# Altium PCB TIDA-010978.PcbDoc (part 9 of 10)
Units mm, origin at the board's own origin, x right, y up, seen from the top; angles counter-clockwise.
Board outline 243.95 x 94.85 mm, 4 copper layers (Top Layer, Mid Layer 1, Mid Layer 2, Bottom Layer), stack 1.623 mm thick; 865 components, 374 nets, 2308 pads, 2132 vias.
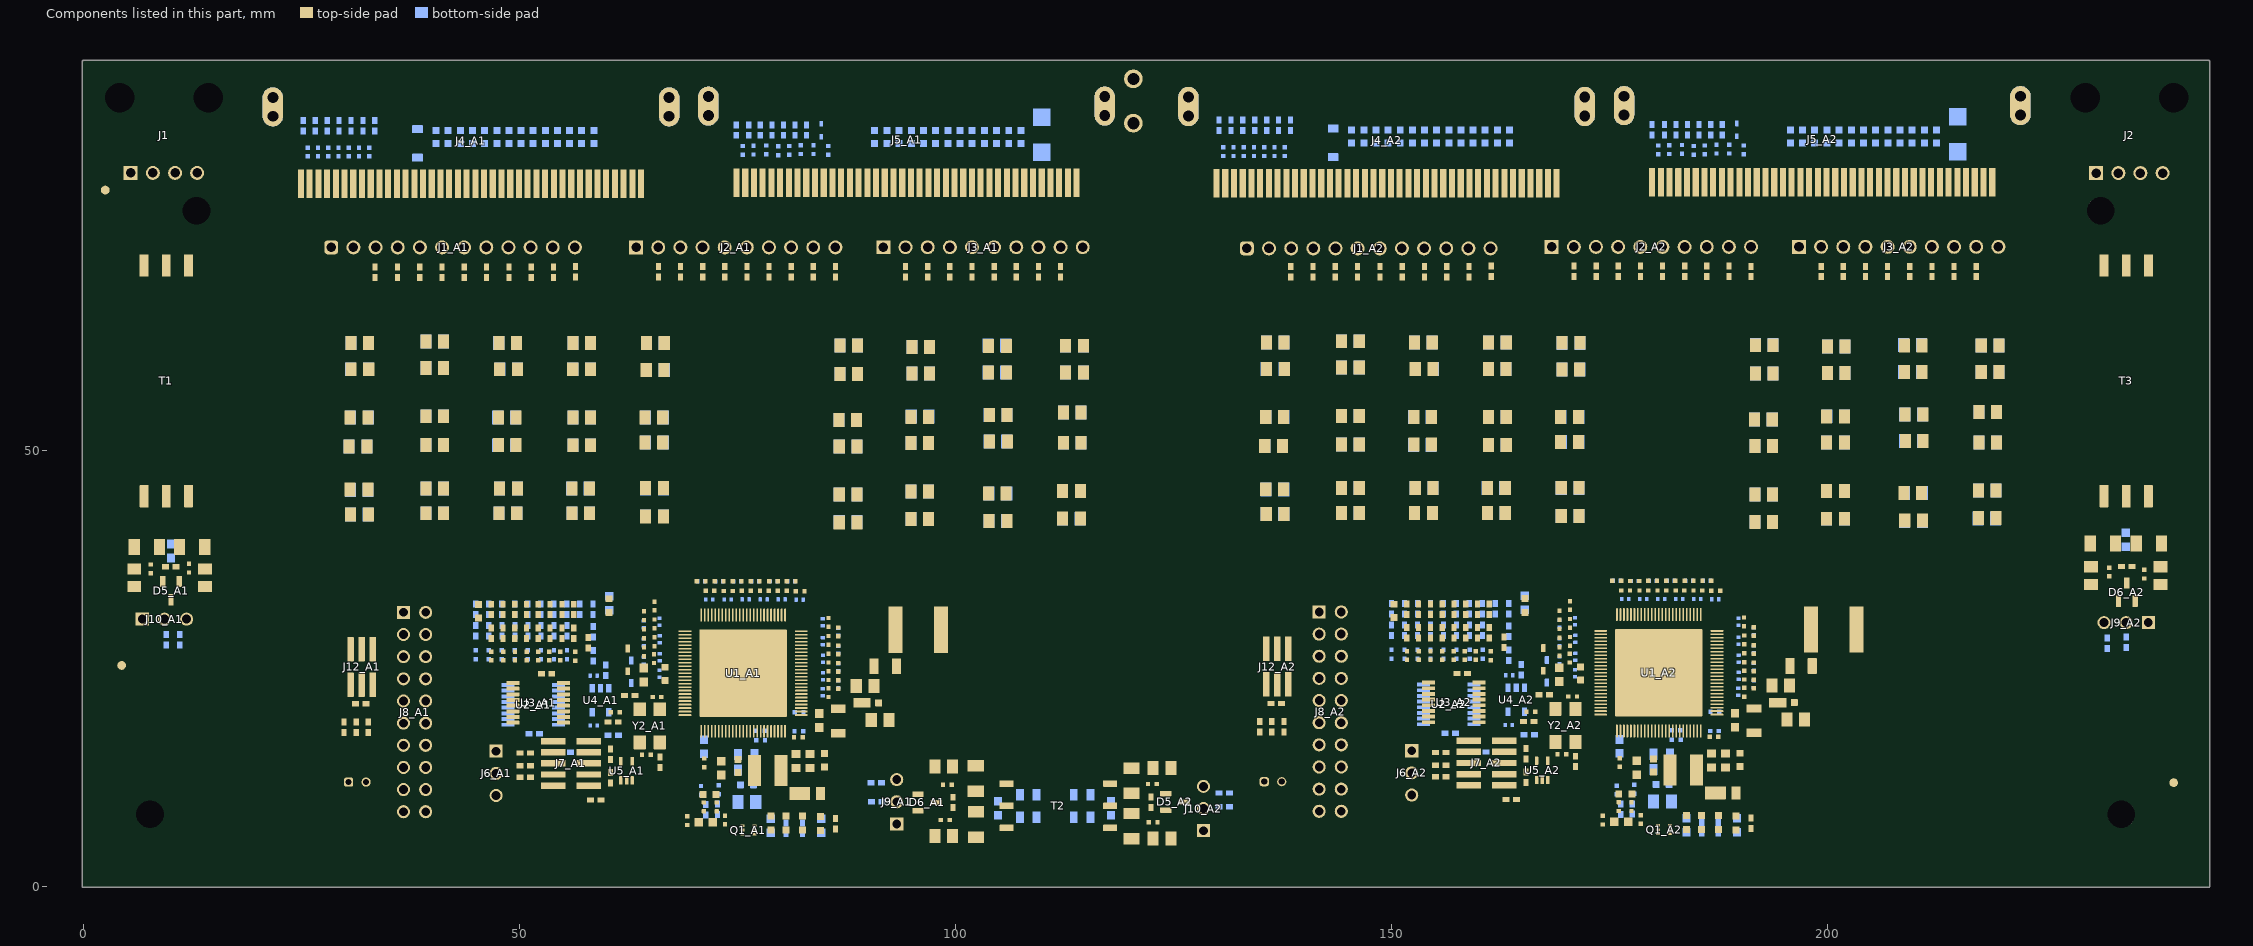
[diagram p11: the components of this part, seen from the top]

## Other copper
Top Layer:
  region net CB20_A2: 204.464,57.058 201.292,57.058 201.292,63.945 204.464,63.945
  region net CELL20_A2: 200.886,57.058 197.715,57.058 197.715,63.945 200.886,63.945
  region net CB17_A2: 196.058,56.967 192.886,56.967 192.886,63.854 196.058,63.854
  region net CELL17_A2: 192.48,56.967 189.308,56.967 189.308,63.854 192.48,63.854
  region net CB14_A2: 174.013,57.338 170.841,57.338 170.841,64.225 174.013,64.225
  region net CELL14_A2: 170.435,57.338 167.263,57.338 167.263,64.225 170.435,64.225
  pour cut-out: 198.148,82.352 198.148,83.282 198.953,84.087 212.953,84.087 213.996,83.044 213.996,82.198
  region net CB26_A2: 221.919,57.058 218.748,57.058 218.748,63.945 221.919,63.945
  region net CELL26_A2: 218.342,57.058 215.17,57.058 215.17,63.945 218.342,63.945
  region net CB23_A2: 213.251,57.058 210.08,57.058 210.08,63.945 213.251,63.945
  region net CELL23_A2: 209.674,57.058 206.502,57.058 206.502,63.945 209.674,63.945
  region net CELL25_A2: 218.273,49.233 215.101,49.233 215.101,56.12 218.273,56.12
  region net CB22_A2: 213.359,49.078 210.188,49.078 210.188,55.965 213.359,55.965
  region net CELL22_A2: 209.782,49.078 206.61,49.078 206.61,55.965 209.782,55.965
  region net CB24_A2: 221.72,40.608 218.548,40.608 218.548,47.495 221.72,47.495
  region net CELL24_A2: 218.143,40.608 214.971,40.608 214.971,47.495 218.143,47.495
  region net CB21_A2: 213.229,40.453 210.058,40.453 210.058,47.34 213.229,47.34
  region net CELL21_A2: 209.652,40.453 206.48,40.453 206.48,47.34 209.652,47.34
  region net CB19_A2: 204.518,49.062 201.347,49.062 201.347,55.949 204.518,55.949
  region net CELL19_A2: 200.941,49.062 197.769,49.062 197.769,55.949 200.941,55.949
  region net CB16_A2: 196.144,48.79 192.973,48.79 192.973,55.677 196.144,55.677
  region net CELL16_A2: 192.567,48.79 189.395,48.79 189.395,55.677 192.567,55.677
  region net CB18_A2: 204.388,40.437 201.217,40.437 201.217,47.324 204.388,47.324
  region net CELL18_A2: 200.811,40.437 197.639,40.437 197.639,47.324 200.811,47.324
  region net CB15_A2: 196.014,40.165 192.843,40.165 192.843,47.052 196.014,47.052
  region net CELL15_A2: 192.437,40.165 189.265,40.165 189.265,47.052 192.437,47.052
  pour cut-out: 148.223,82.339 148.223,78.896 143.417,78.896 139.729,75.209 137.264,75.209 134.449,72.394 134.449,67.325 140.505,67.325 142.586,65.245 167.392,65.245 167.392,65.024 168.207,64.209 175.49,64.209 175.49,39.879 174.974,39.363 168.198,39.363 168.198,39.361 166.645,37.591 166.645,27.723 168.492,25.876 171.69,25.876 173.327,24.238 173.327,24.099 174.373,24.099 174.747,24.473 174.607,24.614 174.607,30.549 185.568,30.549 186.466,29.651 186.707,29.651 186.707,22.852 186.03,22.175 185.858,22.175 185.858,19.366 186.73,18.495 192.295,18.474 192.865,17.841 200.704,17.841 200.704,25.885 202.072,25.885 202.072,32.583 202.091,32.603 201.407,33.286 196.716,33.286 196.716,35.241 197.412,35.937 225.967,35.937 225.967,67.262 222.842,70.387 222.842,75.612 219.112,75.612 215.892,78.832 215.892,82.033
  region net CB12_A2: 173.86,40.725 170.689,40.725 170.689,47.612 173.86,47.612
  region net CB13_A2: 173.764,49.038 170.592,49.038 170.592,55.925 173.764,55.925
  region net CELL12_A2: 170.283,40.725 167.111,40.725 167.111,47.612 170.283,47.612
  region net CELL13_A2: 170.187,49.038 167.015,49.038 167.015,55.925 170.187,55.925
  region net CB25_A2: 221.85,49.233 218.678,49.233 218.678,56.12 221.85,56.12
  pour cut-out: 148.223,82.552 148.223,83.482 149.028,84.287 163.028,84.287 164.071,83.244 164.071,82.398
  region net CB11_A2: 165.607,57.507 162.435,57.507 162.435,64.393 165.607,64.393
  region net CELL11_A2: 162.03,57.507 158.858,57.507 158.858,64.393 162.03,64.393
  region net CB8_A2: 157.082,57.507 153.91,57.507 153.91,64.393 157.082,64.393
  region net CELL8_A2: 153.505,57.507 150.333,57.507 150.333,64.393 153.505,64.393
  region net CB5_A2: 148.582,57.507 145.41,57.507 145.41,64.393 148.582,64.393
  region net CELL5_A2: 145.005,57.507 141.833,57.507 141.833,64.393 145.005,64.393
  region net CB2_A2: 140.072,57.566 136.9,57.566 136.9,64.453 140.072,64.453
  region net CELL2_A2: 136.494,57.566 133.323,57.566 133.323,64.453 136.494,64.453
  region net CB10_A2: 165.477,49.007 162.305,49.007 162.305,55.893 165.477,55.893
  region net CELL10_A2: 161.9,49.007 158.728,49.007 158.728,55.893 161.9,55.893
  region net CB9_A2: 165.573,40.693 162.401,40.693 162.401,47.58 165.573,47.58
  region net CELL9_A2: 161.996,40.693 158.824,40.693 158.824,47.58 161.996,47.58
  region net CB7_A2: 156.952,49.007 153.78,49.007 153.78,55.893 156.952,55.893
  pour cut-out: 175.49,64.209 174.416,65.283 143.124,65.283 141.374,67.034 131.669,67.034 131.669,41.085 133.404,39.35 175.765,39.35 175.765,40.195 176.838,41.267 176.838,64.146
  region net CELL7_A2: 153.375,49.007 150.203,49.007 150.203,55.893 153.375,55.893
  region net CB6_A2: 157.048,40.693 153.876,40.693 153.876,47.58 157.048,47.58
  region net CELL6_A2: 153.471,40.693 150.299,40.693 150.299,47.58 153.471,47.58
  region net CELL0_A2: 136.446,40.693 133.274,40.693 133.274,47.58 136.446,47.58
  region net CELL1_A2: 136.35,49.007 133.178,49.007 133.178,55.893 136.35,55.893
  region net CB0_A2: 139.856,40.693 136.685,40.693 136.685,47.58 139.856,47.58
  region net CB1_A2: 139.927,49.007 136.755,49.007 136.755,55.893 139.927,55.893
  region net CB4_A2: 148.452,49.007 145.28,49.007 145.28,55.893 148.452,55.893
  region net CELL4_A2: 144.875,49.007 141.703,49.007 141.703,55.893 144.875,55.893
  region net CB3_A2: 148.548,40.693 145.376,40.693 145.376,47.58 148.548,47.58
  region net CELL3_A2: 144.971,40.693 141.799,40.693 141.799,47.58 144.971,47.58
  pour cut-out: 183.606,16.121 183.472,15.987 183.472,10.912 185.33,10.912 185.371,10.871 185.371,9.318 188.529,9.318 188.908,9.698 188.908,12.108 189.507,12.135 189.495,16.157
  region net SW_A2: 184.189,11.77 184.189,15.51 184.394,15.715 187.232,15.715 187.232,12.794 187.232,12.673 188.325,11.58 188.315,11.58 188.325,10.289 188.226,10.19 185.915,10.19 185.915,11.24 185.385,11.77
  pour cut-out: 148.223,82.427 148.223,78.896 143.417,78.896 139.729,75.209 137.264,75.209 134.449,72.394 134.449,67.325 140.505,67.325 142.586,65.245 167.392,65.245 167.392,65.024 168.207,64.209 175.49,64.209 175.49,39.879 174.974,39.363 168.198,39.363 168.198,39.361 166.645,37.591 166.645,27.723 168.492,25.876 171.69,25.876 173.327,24.238 173.327,24.099 174.373,24.099 174.747,24.473 174.607,24.614 174.607,30.549 185.568,30.549 186.466,29.651 186.707,29.651 186.707,22.852 186.03,22.175 185.858,22.175 185.858,19.366 186.538,18.686 192.284,18.686 194.548,17.536 200.704,17.545 200.704,25.885 202.072,25.885 202.072,32.583 202.091,32.603 201.407,33.286 196.716,33.286 196.716,35.241 197.412,35.937 225.967,35.937 225.967,67.262 222.842,70.387 222.842,75.612 219.112,75.612 215.892,78.832 215.892,82.122
  pour cut-out: 43.223,82.289 43.223,78.846 38.417,78.846 34.729,75.159 32.264,75.159 29.449,72.344 29.449,67.275 35.505,67.275 37.586,65.195 62.392,65.195 62.392,64.974 63.207,64.159 70.49,64.159 70.49,39.829 69.974,39.313 63.198,39.313 63.198,39.311 61.645,37.541 61.645,27.673 63.492,25.826 66.69,25.826 68.327,24.188 68.327,24.049 69.373,24.049 69.747,24.423 69.607,24.564 69.607,30.499 80.568,30.499 81.466,29.601 81.707,29.601 81.707,22.802 81.03,22.125 80.858,22.125 80.858,19.316 81.73,18.445 87.295,18.424 87.997,17.644 95.704,17.644 95.704,25.835 97.072,25.835 97.072,32.533 97.091,32.553 96.407,33.236 91.716,33.236 91.716,35.191 92.412,35.887 120.967,35.887 120.967,67.212 117.842,70.337 117.842,75.562 114.112,75.562 110.892,78.782 110.892,81.983
  pour cut-out: 183.606,16.121 183.472,15.987 183.472,10.912 185.33,10.912 185.371,10.871 185.371,9.318 188.529,9.318 188.908,9.698 188.908,12.108 189.507,12.135 189.495,16.157
  pour cut-out: 78.606,16.071 78.472,15.937 78.472,10.862 80.33,10.862 80.371,10.821 80.371,9.268 83.529,9.268 83.908,9.648 83.908,12.058 84.507,12.085 84.495,16.107
  region net SW_A1: 79.189,11.72 79.189,15.46 79.394,15.665 82.232,15.665 82.232,12.744 82.232,12.623 83.325,11.53 83.315,11.53 83.325,10.239 83.226,10.14 80.915,10.14 80.915,11.19 80.385,11.72
  pour cut-out: 106.393,15.358 106.393,3.936 117.032,3.936 117.032,15.358
  pour cut-out: 106.401,15.465 106.401,4.043 117.039,4.043 117.039,15.465
  pour cut-out: 198.148,82.352 198.148,84.087 213.996,84.087 213.996,82.198
  pour cut-out: 175.49,64.209 174.416,65.283 143.124,65.283 141.374,67.034 131.669,67.034 131.669,41.085 133.404,39.35 175.765,39.35 175.765,40.195 176.838,41.267 176.838,64.146
  pour cut-out: 148.223,82.552 148.223,83.482 149.028,84.287 163.028,84.287 164.071,83.244 164.071,82.398
  pour cut-out: 162.636,25.219 168.106,25.219 168.433,24.892 168.433,21.879 170.055,21.879 170.855,22.678 172.974,22.678 173.541,22.112 174.828,22.112 174.985,21.955 174.985,21.687 174.717,21.687 174.514,21.484 173.336,21.484 172.59,20.739 172.59,14.819 168.497,10.725 168.497,10.461 167.719,9.683 162.648,9.683
  region net CB10_A1: 60.477,48.957 57.305,48.957 57.305,55.843 60.477,55.843
  region net CB7_A1: 51.952,48.957 48.78,48.957 48.78,55.843 51.952,55.843
  region net CELL10_A1: 56.9,48.957 53.728,48.957 53.728,55.843 56.9,55.843
  region net CB8_A1: 52.082,57.457 48.91,57.457 48.91,64.343 52.082,64.343
  region net CELL11_A1: 57.03,57.457 53.858,57.457 53.858,64.343 57.03,64.343
  region net CB11_A1: 60.607,57.457 57.435,57.457 57.435,64.343 60.607,64.343
  region net CELL4_A1: 39.875,48.957 36.703,48.957 36.703,55.843 39.875,55.843
  region net CB4_A1: 43.452,48.957 40.28,48.957 40.28,55.843 43.452,55.843
  region net CELL5_A1: 40.005,57.457 36.833,57.457 36.833,64.343 40.005,64.343
  region net CB5_A1: 43.582,57.457 40.41,57.457 40.41,64.343 43.582,64.343
  region net CELL7_A1: 48.375,48.957 45.203,48.957 45.203,55.843 48.375,55.843
  region net CELL8_A1: 48.505,57.457 45.333,57.457 45.333,64.343 48.505,64.343
  region net CELL2_A1: 31.494,57.516 28.323,57.516 28.323,64.403 31.494,64.403
  region net CELL1_A1: 31.35,48.957 28.178,48.957 28.178,55.843 31.35,55.843
  region net CELL0_A1: 31.446,40.643 28.274,40.643 28.274,47.53 31.446,47.53
  region net CB22_A1: 108.359,49.028 105.188,49.028 105.188,55.915 108.359,55.915
  region net CB19_A1: 99.518,49.012 96.347,49.012 96.347,55.899 99.518,55.899
  region net CELL22_A1: 104.782,49.028 101.61,49.028 101.61,55.915 104.782,55.915
  region net CB24_A1: 116.72,40.558 113.548,40.558 113.548,47.445 116.72,47.445
  region net CELL24_A1: 113.143,40.558 109.971,40.558 109.971,47.445 113.143,47.445
  region net CELL25_A1: 113.273,49.183 110.101,49.183 110.101,56.07 113.273,56.07
  region net CB25_A1: 116.85,49.183 113.678,49.183 113.678,56.07 116.85,56.07
  region net CB12_A1: 68.86,40.675 65.689,40.675 65.689,47.562 68.86,47.562
  region net CELL21_A1: 104.652,40.403 101.48,40.403 101.48,47.29 104.652,47.29
  region net CELL15_A1: 87.437,40.115 84.265,40.115 84.265,47.002 87.437,47.002
  region net CB15_A1: 91.014,40.115 87.843,40.115 87.843,47.002 91.014,47.002
  region net CELL16_A1: 87.567,48.74 84.395,48.74 84.395,55.627 87.567,55.627
  region net CELL26_A1: 113.342,57.008 110.17,57.008 110.17,63.895 113.342,63.895
  region net CELL20_A1: 95.886,57.008 92.715,57.008 92.715,63.895 95.886,63.895
  region net CB20_A1: 99.464,57.008 96.292,57.008 96.292,63.895 99.464,63.895
  region net CELL23_A1: 104.674,57.008 101.502,57.008 101.502,63.895 104.674,63.895
  region net CB23_A1: 108.251,57.008 105.08,57.008 105.08,63.895 108.251,63.895
  region net CELL19_A1: 95.941,49.012 92.769,49.012 92.769,55.899 95.941,55.899
  region net CB16_A1: 91.144,48.74 87.973,48.74 87.973,55.627 91.144,55.627
  region net CB26_A1: 116.919,57.008 113.748,57.008 113.748,63.895 116.919,63.895
  region net CB21_A1: 108.229,40.403 105.058,40.403 105.058,47.29 108.229,47.29
  region net CELL17_A1: 87.48,56.917 84.308,56.917 84.308,63.804 87.48,63.804
  region net CB17_A1: 91.058,56.917 87.886,56.917 87.886,63.804 91.058,63.804
  region net CB1_A1: 34.927,48.957 31.755,48.957 31.755,55.843 34.927,55.843
  region net CB2_A1: 35.072,57.516 31.9,57.516 31.9,64.403 35.072,64.403
  region net CB18_A1: 99.388,40.387 96.217,40.387 96.217,47.274 99.388,47.274
  region net CELL18_A1: 95.811,40.387 92.639,40.387 92.639,47.274 95.811,47.274
  region net CB0_A1: 34.856,40.643 31.685,40.643 31.685,47.53 34.856,47.53
  region net CB13_A1: 68.764,48.988 65.592,48.988 65.592,55.875 68.764,55.875
  region net CELL13_A1: 65.187,48.988 62.015,48.988 62.015,55.875 65.187,55.875
  region net CELL14_A1: 65.435,57.288 62.263,57.288 62.263,64.175 65.435,64.175
  region net CB14_A1: 69.013,57.288 65.841,57.288 65.841,64.175 69.013,64.175
  region net CELL3_A1: 39.971,40.643 36.799,40.643 36.799,47.53 39.971,47.53
  region net CELL12_A1: 65.283,40.675 62.111,40.675 62.111,47.562 65.283,47.562
  region net CB9_A1: 60.573,40.643 57.401,40.643 57.401,47.53 60.573,47.53
  region net CB3_A1: 43.548,40.643 40.376,40.643 40.376,47.53 43.548,47.53
  region net CELL6_A1: 48.471,40.643 45.299,40.643 45.299,47.53 48.471,47.53
  region net CB6_A1: 52.048,40.643 48.876,40.643 48.876,47.53 52.048,47.53
  region net CELL9_A1: 56.996,40.643 53.824,40.643 53.824,47.53 56.996,47.53
  pour cut-out: 70.49,64.159 69.416,65.233 38.124,65.233 36.374,66.984 26.669,66.984 26.669,41.035 28.404,39.3 70.765,39.3 70.765,40.145 71.838,41.217 71.838,64.096
  pour cut-out: 93.148,82.302 93.148,84.037 108.996,84.037 108.996,82.148
  pour cut-out: 43.223,82.502 43.223,83.432 44.028,84.237 58.028,84.237 59.071,83.194 59.071,82.348
  text ".Layer_Name" at 14.656,-21.806 h1.52
Mid Layer 1:
  pour cut-out: 195.707,74.642 194.984,74.642 194.501,74.158 194.501,72.086 195.16,71.427 221.981,71.427 221.981,74.752 221.756,74.977 195.695,74.977
  pour cut-out: 167.345,74.629 166.623,74.629 166.139,74.145 166.139,72.072 166.798,71.414 193.62,71.414 193.62,74.738 193.395,74.964 167.334,74.964
  pour cut-out: 195.707,74.642 194.984,74.642 194.501,74.158 194.501,72.086 195.16,71.427 221.981,71.427 221.981,74.752 221.756,74.977 195.695,74.977
  pour cut-out: 197.565,83.567 198.042,84.045 214.579,84.045 214.579,82.106 197.565,82.106
  pour cut-out: 145.56,83.786 146.037,84.263 163.291,84.263 163.291,82.325 145.56,82.325
  pour cut-out: 137.471,74.629 136.748,74.629 136.265,74.145 136.265,72.072 136.924,71.414 163.746,71.414 163.746,74.738 163.52,74.964 137.459,74.964
  pour cut-out: 106.382,15.34 106.382,3.919 117.021,3.919 117.021,15.34
  pour cut-out: 167.345,74.629 166.623,74.629 166.139,74.145 166.139,72.072 166.798,71.414 193.62,71.414 193.62,74.738 193.395,74.964 167.334,74.964
  pour cut-out: 197.565,83.567 198.042,84.045 214.579,84.045 214.579,82.106 197.565,82.106
  pour cut-out: 137.471,74.629 136.748,74.629 136.265,74.145 136.265,72.072 136.924,71.414 163.746,71.414 163.746,74.738 163.52,74.964 137.459,74.964
  pour cut-out: 145.56,83.786 146.037,84.263 163.291,84.263 163.291,82.325 145.56,82.325
  pour cut-out: 32.471,74.579 31.748,74.579 31.265,74.095 31.265,72.023 31.924,71.364 58.746,71.364 58.746,74.688 58.52,74.914 32.459,74.914
  pour cut-out: 62.345,74.579 61.623,74.579 61.139,74.095 61.139,72.023 61.798,71.364 88.62,71.364 88.62,74.688 88.395,74.914 62.334,74.914
  pour cut-out: 90.707,74.592 89.984,74.592 89.501,74.108 89.501,72.036 90.16,71.377 116.981,71.377 116.981,74.702 116.756,74.927 90.695,74.927
  pour cut-out: 40.56,83.736 41.037,84.213 58.291,84.213 58.291,82.275 40.56,82.275
  pour cut-out: 92.565,83.517 93.042,83.995 109.579,83.995 109.579,82.056 92.565,82.056
Mid Layer 2:
  pour cut-out: 195.715,74.615 194.992,74.615 194.509,74.132 194.509,72.059 195.168,71.4 221.99,71.4 221.99,74.725 221.764,74.95 195.703,74.95
  pour cut-out: 197.573,83.541 198.051,84.018 214.587,84.018 214.587,82.079 197.573,82.079
  pour cut-out: 167.353,74.602 166.631,74.602 166.147,74.118 166.147,72.046 166.806,71.387 193.628,71.387 193.628,74.712 193.403,74.937 167.342,74.937
  pour cut-out: 145.568,83.76 146.045,84.237 163.299,84.237 163.299,82.298 145.568,82.298
  pour cut-out: 137.479,74.602 136.757,74.602 136.273,74.118 136.273,72.046 136.932,71.387 163.754,71.387 163.754,74.712 163.528,74.937 137.467,74.937
  pour cut-out: 106.382,15.34 106.382,3.919 117.021,3.919 117.021,15.34
  pour cut-out: 197.573,83.541 198.051,84.018 214.587,84.018 214.587,82.079 197.573,82.079
  pour cut-out: 145.568,83.76 146.045,84.237 163.299,84.237 163.299,82.298 145.568,82.298
  pour cut-out: 167.353,74.602 166.631,74.602 166.147,74.118 166.147,72.046 166.806,71.387 193.628,71.387 193.628,74.712 193.403,74.937 167.342,74.937
  pour cut-out: 137.479,74.602 136.757,74.602 136.273,74.118 136.273,72.046 136.932,71.387 163.754,71.387 163.754,74.712 163.528,74.937 137.467,74.937
  pour cut-out: 90.715,74.565 89.992,74.565 89.509,74.082 89.509,72.009 90.168,71.35 116.99,71.35 116.99,74.675 116.764,74.9 90.703,74.9
  pour cut-out: 62.353,74.552 61.631,74.552 61.147,74.068 61.147,71.996 61.806,71.337 88.628,71.337 88.628,74.662 88.403,74.887 62.342,74.887
  pour cut-out: 32.479,74.552 31.757,74.552 31.273,74.068 31.273,71.996 31.932,71.337 58.754,71.337 58.754,74.662 58.528,74.887 32.467,74.887
  pour cut-out: 40.568,83.71 41.045,84.187 58.299,84.187 58.299,82.248 40.568,82.248
  pour cut-out: 92.573,83.491 93.05,83.968 109.587,83.968 109.587,82.029 92.573,82.029
Bottom Layer:
  pour cut-out: 195.715,74.615 194.992,74.615 194.509,74.132 194.509,72.059 195.168,71.4 221.99,71.4 221.99,74.725 221.764,74.95 195.703,74.95
  pour cut-out: 90.715,74.565 89.992,74.565 89.509,74.082 89.509,72.009 90.168,71.35 116.99,71.35 116.99,74.675 116.764,74.9 90.703,74.9
  pour cut-out: 176.597,18.521 176.322,18.796 172.94,18.796 171.651,17.507 170.249,17.507 170.155,17.413 170.155,11.127 170.811,10.471 174.163,10.471 174.581,11.127 174.581,11.565 174.581,16.762 175.013,16.762 175.326,17.507 176.094,17.6 176.597,17.6
  region net CB10_A2: 165.477,49.007 162.305,49.007 162.305,55.893 165.477,55.893
  region net CB9_A2: 165.573,40.693 162.401,40.693 162.401,47.58 165.573,47.58
  region net CELL10_A2: 161.9,49.007 158.728,49.007 158.728,55.893 161.9,55.893
  region net CB7_A2: 156.952,49.007 153.78,49.007 153.78,55.893 156.952,55.893
  region net CELL7_A2: 153.375,49.007 150.203,49.007 150.203,55.893 153.375,55.893
  region net CELL9_A2: 161.996,40.693 158.824,40.693 158.824,47.58 161.996,47.58
  region net CB6_A2: 157.048,40.693 153.876,40.693 153.876,47.58 157.048,47.58
  region net CELL6_A2: 153.471,40.693 150.299,40.693 150.299,47.58 153.471,47.58
  region net CB4_A2: 148.452,49.007 145.28,49.007 145.28,55.893 148.452,55.893
  region net CELL4_A2: 144.875,49.007 141.703,49.007 141.703,55.893 144.875,55.893
  region net CB3_A2: 148.548,40.693 145.376,40.693 145.376,47.58 148.548,47.58
  region net CELL3_A2: 144.971,40.693 141.799,40.693 141.799,47.58 144.971,47.58
  region net CB2_A2: 140.057,57.632 136.885,57.632 136.885,64.518 140.057,64.518
  region net CELL2_A2: 136.48,57.632 133.308,57.632 133.308,64.518 136.48,64.518
  region net CB1_A2: 139.927,49.007 136.755,49.007 136.755,55.893 139.927,55.893
  region net CELL1_A2: 136.35,49.007 133.178,49.007 133.178,55.893 136.35,55.893
  region net CB0_A2: 139.856,40.693 136.685,40.693 136.685,47.58 139.856,47.58
  region net CELL0_A2: 136.446,40.693 133.274,40.693 133.274,47.58 136.446,47.58
  region net CELL23_A2: 209.674,57.058 206.502,57.058 206.502,63.945 209.674,63.945
  region net CB20_A2: 204.464,57.058 201.292,57.058 201.292,63.945 204.464,63.945
  region net CELL20_A2: 200.886,57.058 197.715,57.058 197.715,63.945 200.886,63.945
  region net CELL22_A2: 209.782,49.078 206.61,49.078 206.61,55.965 209.782,55.965
  region net CELL19_A2: 200.941,49.062 197.769,49.062 197.769,55.949 200.941,55.949
  region net CB19_A2: 204.518,49.062 201.347,49.062 201.347,55.949 204.518,55.949
  region net CB17_A2: 196.058,56.967 192.886,56.967 192.886,63.854 196.058,63.854
  region net CB16_A2: 196.144,48.79 192.973,48.79 192.973,55.677 196.144,55.677
  region net CELL17_A2: 192.48,56.967 189.308,56.967 189.308,63.854 192.48,63.854
  region net CELL16_A2: 192.567,48.79 189.395,48.79 189.395,55.677 192.567,55.677
  pour cut-out: 137.55,74.854 130.547,67.852 130.547,40.184 134.844,35.888 162.977,35.888 164.625,34.24 166.417,34.24 166.417,27.447 167.99,25.874 172.603,25.874 174.086,24.391 175.575,24.391 175.563,24.402 175.563,29.496 175.819,29.751 175.825,29.745 185.59,29.745 185.988,29.347 185.96,29.319 185.96,21.605 188.16,21.605 188.717,21.047 191.081,21.047 191.774,21.741 195.2,21.741 195.2,22.19 209.464,36.454 222.5,36.454 225.4,39.354 225.4,63.891 218.355,70.935 218.355,74.529
  region net CB24_A2: 221.72,40.608 218.548,40.608 218.548,47.495 221.72,47.495
  region net CELL24_A2: 218.143,40.608 214.971,40.608 214.971,47.495 218.143,47.495
  region net CB21_A2: 213.229,40.453 210.058,40.453 210.058,47.34 213.229,47.34
  region net CELL21_A2: 209.652,40.453 206.48,40.453 206.48,47.34 209.652,47.34
  region net CB18_A2: 204.388,40.437 201.217,40.437 201.217,47.324 204.388,47.324
  region net CELL18_A2: 200.811,40.437 197.639,40.437 197.639,47.324 200.811,47.324
  region net CB15_A2: 196.014,40.165 192.843,40.165 192.843,47.052 196.014,47.052
  region net CELL15_A2: 192.437,40.165 189.265,40.165 189.265,47.052 192.437,47.052
  region net CB14_A2: 174.013,57.338 170.841,57.338 170.841,64.225 174.013,64.225
  region net CELL14_A2: 170.435,57.338 167.263,57.338 167.263,64.225 170.435,64.225
  region net CB11_A2: 165.607,57.507 162.435,57.507 162.435,64.393 165.607,64.393
  region net CELL11_A2: 162.03,57.507 158.858,57.507 158.858,64.393 162.03,64.393
  pour cut-out: 145.042,85.712 145.042,84.629 145.183,84.489 146.472,84.489 148.582,82.378 148.602,82.398 164.071,82.398 164.071,84.09 165.209,85.229 165.209,86.237 145.514,86.237 145.439,86.162
  region net CB8_A2: 157.082,57.507 153.91,57.507 153.91,64.393 157.082,64.393
  region net CELL8_A2: 153.505,57.507 150.333,57.507 150.333,64.393 153.505,64.393
  region net CB13_A2: 173.764,49.038 170.592,49.038 170.592,55.925 173.764,55.925
  region net CELL13_A2: 170.187,49.038 167.015,49.038 167.015,55.925 170.187,55.925
  region net CB12_A2: 173.86,40.725 170.689,40.725 170.689,47.612 173.86,47.612
  region net CELL12_A2: 170.283,40.725 167.111,40.725 167.111,47.612 170.283,47.612
  region net CELL5_A2: 145.005,57.507 141.833,57.507 141.833,64.393 145.005,64.393
  region net CB5_A2: 148.582,57.507 145.41,57.507 145.41,64.393 148.582,64.393
  region net CB26_A2: 221.919,57.058 218.748,57.058 218.748,63.945 221.919,63.945
  region net CELL26_A2: 218.342,57.058 215.17,57.058 215.17,63.945 218.342,63.945
  region net CB23_A2: 213.251,57.058 210.08,57.058 210.08,63.945 213.251,63.945
  region net CB25_A2: 221.85,49.233 218.678,49.233 218.678,56.12 221.85,56.12
  region net CELL25_A2: 218.273,49.233 215.101,49.233 215.101,56.12 218.273,56.12
  region net CB22_A2: 213.359,49.078 210.188,49.078 210.188,55.965 213.359,55.965
  pour cut-out: 194.642,86.437 194.637,86.432 194.637,84.537 194.639,84.537 197.439,81.737 216.512,81.737 217.355,82.58 217.355,86.497
  pour cut-out: 106.382,15.34 106.382,3.919 117.021,3.919 117.021,15.34
  pour cut-out: 137.55,74.854 130.547,67.852 130.547,40.184 134.844,35.888 162.977,35.888 164.625,34.24 166.417,34.24 166.417,27.447 167.99,25.874 172.603,25.874 174.086,24.391 175.575,24.391 175.563,24.402 175.563,29.496 175.819,29.751 175.825,29.745 185.59,29.745 185.988,29.347 185.96,29.319 185.96,21.605 188.16,21.605 188.717,21.047 191.081,21.047 191.774,21.741 195.2,21.741 195.2,22.19 209.464,36.454 222.5,36.454 225.4,39.354 225.4,63.891 218.355,70.935 218.355,74.529
  pour cut-out: 145.042,85.712 145.042,84.629 145.183,84.489 146.472,84.489 148.582,82.378 148.602,82.398 164.071,82.398 164.071,84.09 165.209,85.229 165.209,86.237 145.514,86.237 145.439,86.162
  pour cut-out: 194.642,86.437 194.637,86.432 194.637,84.537 194.639,84.537 197.439,81.737 216.512,81.737 217.355,82.58 217.355,86.497
  pour cut-out: 174.607,22.499 174.332,22.774 170.95,22.774 169.661,21.484 168.259,21.484 168.165,21.391 168.165,15.104 168.821,14.449 172.173,14.449 172.59,15.104 172.59,15.543 172.59,20.739 173.023,20.739 173.336,21.484 174.103,21.577 174.607,21.577
  region net CELL18_A1: 95.811,40.387 92.639,40.387 92.639,47.274 95.811,47.274
  region net CELL19_A1: 95.941,49.012 92.769,49.012 92.769,55.899 95.941,55.899
  region net CELL12_A1: 65.283,40.675 62.111,40.675 62.111,47.562 65.283,47.562
  region net CB12_A1: 68.86,40.675 65.689,40.675 65.689,47.562 68.86,47.562
  region net CELL13_A1: 65.187,48.988 62.015,48.988 62.015,55.875 65.187,55.875
  region net CB13_A1: 68.764,48.988 65.592,48.988 65.592,55.875 68.764,55.875
  region net CB15_A1: 91.014,40.115 87.843,40.115 87.843,47.002 91.014,47.002
  region net CELL15_A1: 87.437,40.115 84.265,40.115 84.265,47.002 87.437,47.002
  region net CELL16_A1: 87.567,48.74 84.395,48.74 84.395,55.627 87.567,55.627
  region net CB16_A1: 91.144,48.74 87.973,48.74 87.973,55.627 91.144,55.627
  region net CB6_A1: 52.048,40.643 48.876,40.643 48.876,47.53 52.048,47.53
  region net CELL6_A1: 48.471,40.643 45.299,40.643 45.299,47.53 48.471,47.53
  region net CB8_A1: 52.082,57.457 48.91,57.457 48.91,64.343 52.082,64.343
  region net CELL8_A1: 48.505,57.457 45.333,57.457 45.333,64.343 48.505,64.343
  region net CELL9_A1: 56.996,40.643 53.824,40.643 53.824,47.53 56.996,47.53
  region net CB9_A1: 60.573,40.643 57.401,40.643 57.401,47.53 60.573,47.53
  region net CB3_A1: 43.548,40.643 40.376,40.643 40.376,47.53 43.548,47.53
  region net CB4_A1: 43.452,48.957 40.28,48.957 40.28,55.843 43.452,55.843
  region net CELL4_A1: 39.875,48.957 36.703,48.957 36.703,55.843 39.875,55.843
  region net CELL1_A1: 31.35,48.957 28.178,48.957 28.178,55.843 31.35,55.843
  region net CB1_A1: 34.927,48.957 31.755,48.957 31.755,55.843 34.927,55.843
  region net CB10_A1: 60.477,48.957 57.305,48.957 57.305,55.843 60.477,55.843
  region net CELL10_A1: 56.9,48.957 53.728,48.957 53.728,55.843 56.9,55.843
  region net CB7_A1: 51.952,48.957 48.78,48.957 48.78,55.843 51.952,55.843
  region net CELL7_A1: 48.375,48.957 45.203,48.957 45.203,55.843 48.375,55.843
  region net CELL2_A1: 31.48,57.582 28.308,57.582 28.308,64.468 31.48,64.468
  region net CB5_A1: 43.582,57.457 40.41,57.457 40.41,64.343 43.582,64.343
  region net CELL5_A1: 40.005,57.457 36.833,57.457 36.833,64.343 40.005,64.343
  region net CB2_A1: 35.057,57.582 31.885,57.582 31.885,64.468 35.057,64.468
  region net CELL11_A1: 57.03,57.457 53.858,57.457 53.858,64.343 57.03,64.343
  region net CB11_A1: 60.607,57.457 57.435,57.457 57.435,64.343 60.607,64.343
  region net CELL3_A1: 39.971,40.643 36.799,40.643 36.799,47.53 39.971,47.53
  region net CELL17_A1: 87.48,56.917 84.308,56.917 84.308,63.804 87.48,63.804
  region net CB17_A1: 91.058,56.917 87.886,56.917 87.886,63.804 91.058,63.804
  region net CELL14_A1: 65.435,57.288 62.263,57.288 62.263,64.175 65.435,64.175
  region net CB14_A1: 69.013,57.288 65.841,57.288 65.841,64.175 69.013,64.175
  region net CELL20_A1: 95.886,57.008 92.715,57.008 92.715,63.895 95.886,63.895
  region net CELL0_A1: 31.446,40.643 28.274,40.643 28.274,47.53 31.446,47.53
  region net CB0_A1: 34.856,40.643 31.685,40.643 31.685,47.53 34.856,47.53
  region net CB18_A1: 99.388,40.387 96.217,40.387 96.217,47.274 99.388,47.274
  region net CB19_A1: 99.518,49.012 96.347,49.012 96.347,55.899 99.518,55.899
  region net CB21_A1: 108.229,40.403 105.058,40.403 105.058,47.29 108.229,47.29
  region net CB24_A1: 116.72,40.558 113.548,40.558 113.548,47.445 116.72,47.445
  region net CELL24_A1: 113.143,40.558 109.971,40.558 109.971,47.445 113.143,47.445
  region net CELL21_A1: 104.652,40.403 101.48,40.403 101.48,47.29 104.652,47.29
  region net CELL22_A1: 104.782,49.028 101.61,49.028 101.61,55.915 104.782,55.915
  region net CB22_A1: 108.359,49.028 105.188,49.028 105.188,55.915 108.359,55.915
  region net CELL23_A1: 104.674,57.008 101.502,57.008 101.502,63.895 104.674,63.895
  region net CB23_A1: 108.251,57.008 105.08,57.008 105.08,63.895 108.251,63.895
  region net CB20_A1: 99.464,57.008 96.292,57.008 96.292,63.895 99.464,63.895
  region net CB25_A1: 116.85,49.183 113.678,49.183 113.678,56.07 116.85,56.07
  region net CELL25_A1: 113.273,49.183 110.101,49.183 110.101,56.07 113.273,56.07
  region net CB26_A1: 116.919,57.008 113.748,57.008 113.748,63.895 116.919,63.895
  region net CELL26_A1: 113.342,57.008 110.17,57.008 110.17,63.895 113.342,63.895
  pour cut-out: 71.597,18.471 71.322,18.746 67.94,18.746 66.651,17.457 65.249,17.457 65.155,17.363 65.155,11.077 65.811,10.421 69.163,10.421 69.581,11.077 69.581,11.515 69.581,16.712 70.013,16.712 70.326,17.457 71.094,17.55 71.597,17.55
  pour cut-out: 89.642,86.387 89.637,86.382 89.637,84.487 89.639,84.487 92.439,81.687 111.512,81.687 112.355,82.53 112.355,86.447
  pour cut-out: 40.042,85.662 40.042,84.579 40.183,84.439 41.471,84.439 43.582,82.328 43.602,82.348 59.071,82.348 59.071,84.04 60.209,85.179 60.209,86.187 40.514,86.187 40.439,86.112
  pour cut-out: 32.55,74.804 25.547,67.802 25.547,40.134 29.844,35.838 57.977,35.838 59.625,34.19 61.417,34.19 61.417,27.397 62.99,25.824 67.603,25.824 69.086,24.341 70.575,24.341 70.563,24.352 70.563,29.446 70.819,29.701 70.825,29.695 80.59,29.695 80.988,29.297 80.96,29.269 80.96,21.555 83.16,21.555 83.717,20.997 86.081,20.997 86.774,21.691 90.2,21.691 90.2,22.14 104.464,36.404 117.5,36.404 120.4,39.304 120.4,63.841 113.355,70.885 113.355,74.479
  text ".Layer_Name" at 14.656,-21.806 h1.52
Multi-Layer:
  pour cut-out: 226.485,94.562 243.827,94.562 243.827,41.137 226.488,41.137
  pour cut-out: -0.016,93.754 0.238,94.008 20.492,94.008 20.492,43.192 17.884,40.583 -0.013,40.583
  pour cut-out: 117.039,15.465 117.167,15.593 117.167,20.937 122.02,30.868 121.85,31.039 121.85,34.572 121.56,34.572 119.954,34.572 113.568,34.572 106.382,21.094 106.382,0.865 106.72,0.527 106.837,0.645 116.88,0.645

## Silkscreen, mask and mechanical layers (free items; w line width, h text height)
Top Overlay:
  text "This document can handle board shapes up to about 13in on a side." at 30.01,236.045 h1.52
  text "To re-size the board shape, do the following:" at 31.407,229.743 h1.52
  text "Select lines on M1 Board Outline and delete (easy in single layer mode...shift+s)" at 32.931,226.592 h1.52
  text "Draw a rectangle using lines (example will be for a 4\" x 6\" board" at 32.931,223.441 h1.52
  text "Enter Place Line mode (keyboard pl)" at 38.265,220.29 h1.52
  text "keyboard jo to jump to origin, hit enter" at 38.265,217.138 h1.52
  text "keyboard jl to jump to location, set x to 6000, hit enter twice" at 38.265,213.987 h1.52
  text "keyboard jl to jump to location, set x to 6000 and y to 4000, hit enter twice" at 38.265,210.836 h1.52
  text "keyboard jl to jump to location, set x to 0 and y to 4000, hit enter twice" at 38.265,207.685 h1.52
  text "keyboard jo to jump to origin, hit enter" at 38.265,204.534 h1.52
  text "Hit ESC twice to exit place line mode" at 38.265,201.383 h1.52
  text "Select lines on M1 Board Outline" at 32.931,197.724 h1.52
  text "Menu Design|Board Shape|Define from Selected Objects (keyboard dsd)" at 32.931,195.081 h1.52
  text "If you re-size the board, don't forget to move the drill table strings on the" at 30.01,186.972 h1.52
  text "Drill Drawing Layer...they should be just to the right of your board shape" at 34.912,184.28 h1.52
  text "0" at 148.628,78.008 h0.76
  text "13" at 161.833,78.008 h0.76
  text "G" at 189.425,78.013 h0.76
  text "G" at 84.352,77.849 h0.76
  text "0" at 43.556,77.844 h0.76
  text "13" at 56.76,77.844 h0.76
  text "T15" at 187.092,77.492 h0.76
  text "11" at 183.725,77.365 h0.76
  text "T15" at 82.019,77.328 h0.76
  text "CELL26+" at 111.6,77.319 h0.76
  text "8" at 180.638,77.255 h0.76
  text "8" at 75.691,77.201 h0.76
  text "11" at 78.652,77.201 h0.76
  text "T7" at 136.359,77.192 h0.76
  text "4" at 133.775,77.127 h0.76
  text "T7" at 31.286,77.028 h0.76
  text "4" at 28.702,76.963 h0.76
  text "1" at 130.905,76.929 h0.76
  text "1" at 25.832,76.765 h0.76
  text "19" at 198.582,76.276 h0.76
  text "20" at 200.905,76.276 h0.76
  text "21" at 203.481,76.276 h0.76
  text "22" at 206.058,76.276 h0.76
  text "23" at 208.634,76.276 h0.76
  text "24" at 211.211,76.276 h0.76
  text "25" at 213.787,76.276 h0.76
  text "26" at 216.364,76.276 h0.76
  text "PWR" at 218.94,76.276 h0.76
  text "10" at 170.453,76.258 h0.76
  text "11" at 172.776,76.258 h0.76
  text "12" at 175.352,76.258 h0.76
  text "13" at 177.929,76.258 h0.76
  text "14" at 180.505,76.258 h0.76
  text "15" at 183.082,76.258 h0.76
  text "16" at 185.658,76.258 h0.76
  text "17" at 188.235,76.258 h0.76
  text "18" at 190.811,76.258 h0.76
  text "18" at 196.005,76.228 h0.76
  text "9" at 167.877,76.21 h0.76
  text "19" at 93.536,76.139 h0.76
  text "20" at 95.859,76.139 h0.76
  text "21" at 98.435,76.139 h0.76
  text "22" at 101.012,76.139 h0.76
  text "23" at 103.588,76.139 h0.76
  text "24" at 106.165,76.139 h0.76
  text "25" at 108.741,76.139 h0.76
  text "26" at 111.318,76.139 h0.76
  text "PWR" at 113.894,76.139 h0.76
  text "10" at 65.407,76.121 h0.76
  text "11" at 67.73,76.121 h0.76
  text "12" at 70.306,76.121 h0.76
  text "13" at 72.883,76.121 h0.76
  text "14" at 75.459,76.121 h0.76
  text "15" at 78.036,76.121 h0.76
  text "16" at 80.612,76.121 h0.76
  text "17" at 83.189,76.121 h0.76
  text "18" at 85.765,76.121 h0.76
  text "9" at 62.83,76.073 h0.76
  text "18" at 90.959,76.091 h0.76
  text "1" at 140.805,76.033 h0.76
  text "2" at 143.128,76.033 h0.76
  text "3" at 145.704,76.033 h0.76
  text "4" at 148.281,76.033 h0.76
  text "5" at 150.858,76.033 h0.76
  text "6" at 153.434,76.033 h0.76
  text "7" at 156.011,76.033 h0.76
  text "8" at 158.587,76.033 h0.76
  text "9" at 161.164,76.033 h0.76
  text "0" at 138.229,75.985 h0.76
  text "1" at 35.759,75.896 h0.76
  text "2" at 38.082,75.896 h0.76
  text "3" at 40.658,75.896 h0.76
  text "4" at 43.235,75.896 h0.76
  text "5" at 45.811,75.896 h0.76
  text "6" at 48.388,75.896 h0.76
  text "7" at 50.965,75.896 h0.76
  text "8" at 53.541,75.896 h0.76
  text "9" at 56.118,75.896 h0.76
  text "G" at 30.79,75.848 h0.76
  text "0" at 33.183,75.848 h0.76
  text "G" at 28.299,75.832 h0.76
  text "CELL27-" at 132.613,75.828 h0.76
  text "G" at 133.289,70.589 h0.76
  text "G" at 135.656,70.609 h0.76
  text "VC" at 135.968,69.268 h0.76
  text "VC" at 30.895,69.104 h0.76
  text "10" at 170.692,67.955 h0.76
  text "11" at 173.015,67.955 h0.76
  text "12" at 175.591,67.955 h0.76
  text "13" at 178.168,67.955 h0.76
  text "14" at 180.744,67.955 h0.76
  text "15" at 183.321,67.955 h0.76
  text "16" at 185.897,67.955 h0.76
  text "17" at 188.474,67.955 h0.76
  text "18" at 191.05,67.955 h0.76
  text "9" at 168.116,67.907 h0.76
  text "19" at 198.582,67.906 h0.76
  text "20" at 200.905,67.906 h0.76
  text "21" at 203.481,67.906 h0.76
  text "22" at 206.058,67.906 h0.76
  text "23" at 208.634,67.906 h0.76
  text "24" at 211.211,67.906 h0.76
  text "25" at 213.787,67.906 h0.76
  text "26" at 216.364,67.906 h0.76
  text "1" at 140.875,67.861 h0.76
  text "2" at 143.198,67.861 h0.76
  text "3" at 145.774,67.861 h0.76
  text "4" at 148.351,67.861 h0.76
  text "5" at 150.927,67.861 h0.76
  text "6" at 153.504,67.861 h0.76
  text "7" at 156.081,67.861 h0.76
  text "8" at 158.657,67.861 h0.76
  text "9" at 161.234,67.861 h0.76
  text "18" at 196.005,67.858 h0.76
  text "10" at 65.619,67.791 h0.76
  text "11" at 67.942,67.791 h0.76
  text "12" at 70.518,67.791 h0.76
  text "13" at 73.095,67.791 h0.76
  text "14" at 75.671,67.791 h0.76
  text "15" at 78.248,67.791 h0.76
  text "16" at 80.825,67.791 h0.76
  text "17" at 83.401,67.791 h0.76
  text "18" at 85.978,67.791 h0.76
  text "0" at 138.299,67.813 h0.76
  text "9" at 63.043,67.743 h0.76
  text "19" at 93.509,67.742 h0.76
  text "20" at 95.832,67.742 h0.76
  text "21" at 98.408,67.742 h0.76
  text "22" at 100.985,67.742 h0.76
  text "23" at 103.561,67.742 h0.76
  text "24" at 106.138,67.742 h0.76
  text "25" at 108.714,67.742 h0.76
  text "26" at 111.291,67.742 h0.76
  text "1" at 35.802,67.697 h0.76
  text "2" at 38.125,67.697 h0.76
  text "3" at 40.702,67.697 h0.76
  text "4" at 43.278,67.697 h0.76
  text "5" at 45.855,67.697 h0.76
  text "6" at 48.431,67.697 h0.76
  text "7" at 51.008,67.697 h0.76
  text "8" at 53.584,67.697 h0.76
  text "9" at 56.161,67.697 h0.76
  text "18" at 90.933,67.694 h0.76
  text "0" at 33.226,67.649 h0.76
  text "CB" at 137.609,65.184 h0.76
  text "CB" at 32.536,65.02 h0.76
  text "CELL" at 134.23,65.01 h0.76
  text "CELL" at 29.157,64.846 h0.76
  text "CB" at 193.079,64.39 h0.76
  text "CB" at 88.006,64.226 h0.76
  text "CELL" at 189.7,64.215 h0.76
  text "CELL" at 84.627,64.051 h0.76
  text "2" at 132.343,60.73 h0.76
  text "11" at 157.763,60.703 h0.76
  text "5" at 140.788,60.659 h0.76
  text "8" at 149.393,60.659 h0.76
  text "14" at 165.684,60.671 h0.76
  text "2" at 27.27,60.566 h0.76
  text "11" at 52.69,60.539 h0.76
  text "14" at 60.611,60.507 h0.76
  text "5" at 35.715,60.495 h0.76
  text "8" at 44.32,60.495 h0.76
  text "17" at 187.968,60.364 h0.76
  text "26" at 213.559,60.346 h0.76
  text "20" at 196.413,60.293 h0.76
  text "23" at 205.018,60.293 h0.76
  text "17" at 82.895,60.2 h0.76
  text "26" at 108.486,60.182 h0.76
  text "20" at 91.34,60.129 h0.76
  text "23" at 99.945,60.129 h0.76
  text "1" at 132.599,52.28 h0.76
  text "10" at 158.02,52.253 h0.76
  text "13" at 165.941,52.221 h0.76
  text "4" at 141.045,52.209 h0.76
  text "7" at 149.649,52.209 h0.76
  text "1" at 27.526,52.116 h0.76
  text "10" at 52.947,52.089 h0.76
  text "4" at 35.972,52.045 h0.76
  text "7" at 44.576,52.045 h0.76
  text "13" at 60.868,52.057 h0.76
  text "16" at 188.224,51.914 h0.76
  text "25" at 213.645,51.887 h0.76
  text "19" at 196.67,51.843 h0.76
  text "22" at 205.274,51.843 h0.76
  text "16" at 83.151,51.75 h0.76
  text "25" at 108.572,51.723 h0.76
  text "19" at 91.597,51.679 h0.76
  text "22" at 100.201,51.679 h0.76
  text "0" at 132.628,44.137 h0.76
  text "9" at 158.048,44.109 h0.76
  text "12" at 165.97,44.077 h0.76
  text "3" at 141.074,44.065 h0.76
  text "6" at 149.678,44.065 h0.76
  text "0" at 27.555,43.973 h0.76
  text "9" at 52.976,43.945 h0.76
  text "3" at 36.001,43.901 h0.76
  text "6" at 44.605,43.901 h0.76
  text "12" at 60.897,43.913 h0.76
  text "15" at 188.253,43.77 h0.76
  text "24" at 213.674,43.743 h0.76
  text "18" at 196.699,43.699 h0.76
  text "21" at 205.303,43.699 h0.76
  text "15" at 83.18,43.606 h0.76
  text "24" at 108.601,43.579 h0.76
  text "18" at 91.626,43.535 h0.76
  text "21" at 100.23,43.535 h0.76
  text "TSREF" at 163.225,35.107 h1.02
  text "TSREF" at 58.152,34.943 h1.02
  text "R1" at 160.935,34.79 h0.76
  text "6" at 158.262,34.756 h0.76
  text "7" at 159.696,34.756 h0.76
  text "T1" at 150.941,34.737 h0.76
  text "2" at 153.011,34.701 h0.76
  text "3" at 154.307,34.701 h0.76
  text "4" at 155.566,34.707 h0.76
  text "5" at 156.874,34.646 h0.76
  text "R1" at 55.862,34.626 h0.76
  text "T1" at 45.868,34.573 h0.76
  text "6" at 53.189,34.592 h0.76
  text "7" at 54.623,34.592 h0.76
  text "4" at 50.493,34.543 h0.76
  text "2" at 47.938,34.537 h0.76
  text "3" at 49.234,34.537 h0.76
  text "5" at 51.802,34.482 h0.76
  text "19" at 141.213,33.861 h0.76
  text "19" at 36.439,33.655 h0.76
  text "7" at 176.132,32.645 h0.76
  text "7" at 71.059,32.481 h0.76
  text "18" at 186.61,32.476 h0.76
  text "6" at 171.155,32.451 h0.76
  text "18" at 81.538,32.311 h0.76
  text "6" at 66.082,32.287 h0.76
  text "20" at 40.954,31.166 h0.76
  text "20" at 145.894,31.166 h0.76
  text "MSPI" at 132.59,31.055 h1.52
  text "MSPI" at 25.341,30.267 h1.52
  text "19" at 188.604,29.295 h0.76
  text "19" at 83.531,29.131 h0.76
  text "18" at 41.08,28.577 h0.76
  text "18" at 146.021,28.577 h0.76
  text "0" at 170.961,26.358 h0.76
  text "0" at 65.888,26.194 h0.76
  text "16" at 41.08,26.113 h0.76
  text "16" at 146.021,26.113 h0.76
  text "GND" at 237.529,25.605 h1.02 r90
  text "H_P" at 232.489,25.452 h1.02 r90
  text "H_N" at 234.684,25.452 h1.02 r90
  text "L_P" at 12.377,24.886 h1.52 r90
  text "L_N" at 9.724,24.756 h1.52 r90
  text "GND" at 7.463,24.536 h1.52 r90
  text "B" at 193.133,24.429 h1.52
  text "B" at 88.389,24.319 h1.52
  text "12" at 41.08,23.613 h0.76
  text "12" at 146.021,23.614 h0.76
  text "P" at 196.857,22.515 h1.52
  text "26" at 188.369,22.317 h0.76
  text "26" at 83.297,22.153 h0.76
  text "18" at 164.481,21.449 h0.76
  text "18" at 59.481,21.399 h0.76
  text "BP" at 85.916,21.263 h1.52
  text "14" at 41.08,20.835 h0.76
  text "14" at 146.021,20.835 h0.76
  text "'.PRJ_Number'.PCB_Rev" at 211.69,20.513 h2.75
  text "10" at 41.08,18.384 h0.76
  text "10" at 146.021,18.384 h0.76
  text "BP" at 193.791,18.06 h1.52 r90
  text "G" at 87.902,17.609 h1.52
  text "17" at 67.8,16.509 h0.76
  text "17" at 173.149,16.317 h0.76
  text "G" at 194.429,16.317 h1.52
  text "H_P" at 91.868,16.009 h1.02
  text "8" at 41.715,15.792 h0.76
  text "8" at 146.656,15.792 h0.76
  text "AVDD" at 42.832,14.904 h0.76
  text "AVDD" at 147.83,14.879 h0.76
  text "H_N" at 91.793,14.362 h1.02
  text "6" at 41.715,13.368 h0.76
  text "6" at 146.656,13.368 h0.76
  text "VIO" at 43.72,12.499 h0.76
  text "VIO" at 148.718,12.474 h0.76
  text "L_P" at 130.343,11.537 h1.02
  text "4" at 41.715,10.83 h0.76
  text "4" at 146.656,10.83 h0.76
  text "EXT33" at 42.07,9.754 h0.76
  text "EXT33" at 147.068,9.729 h0.76
  text "L_N" at 130.343,9.154 h1.02
  text "Shunt" at 27.679,8.204 h1.52
  text "2" at 41.715,8.004 h0.76
  text "2" at 146.656,8.004 h0.76
  text "Shunt" at 133.286,7.544 h1.52
  text "MCUSPI" at 51.454,7.3 h1.52
  text "1" at 36.698,6.259 h0.76
  text "1" at 141.698,6.116 h0.76
  text "MCUSPI" at 157.252,5.881 h1.52
  text "P_N" at 29.081,5.67 h1.52
  text "P_N" at 134.613,5.31 h1.52
  text "GND" at 92.008,3.186 h1.02
  text "GND" at 127.325,2.618 h1.02
  text "FLT" at 190.128,2.535 h0.76 r90
  text "FLT" at 85.056,2.371 h0.76 r90
  text "Mode" at 191.73,2.191 h0.76 r90
  text "Mode" at 86.657,2.027 h0.76 r90
  text "AVDD" at 184.224,1.774 h0.76 r90
  text "DVDD" at 187.821,1.774 h0.76 r90
  text "AVDD" at 79.151,1.61 h0.76 r90
  text "DVDD" at 82.748,1.61 h0.76 r90
  text "LDOIN" at 185.803,1.139 h0.76 r90
  text "LDOIN" at 80.731,0.975 h0.76 r90
  text ".Layer_Name" at 14.656,-21.806 h1.52
Bottom Overlay:
  text "J5_A2" at 201.037,89.231 h1.52
  text "J4_A2" at 145.456,88.629 h1.52
  text "J5_A1" at 94.668,88.452 h1.52
  text "J4_A1" at 39.087,87.85 h1.52
  text "PWR" at 220.454,76.235 h0.76
  text "19" at 199.467,76.208 h0.76
  text "20" at 201.789,76.208 h0.76
  text "21" at 204.366,76.208 h0.76
  text "22" at 206.942,76.208 h0.76
  text "23" at 209.519,76.208 h0.76
  text "24" at 212.096,76.208 h0.76
  text "25" at 214.672,76.208 h0.76
  text "26" at 217.249,76.208 h0.76
  text "10" at 171.338,76.19 h0.76
  text "11" at 173.66,76.19 h0.76
  text "12" at 176.237,76.19 h0.76
  text "13" at 178.813,76.19 h0.76
  text "14" at 181.39,76.19 h0.76
  text "15" at 183.967,76.19 h0.76
  text "16" at 186.543,76.19 h0.76
  text "17" at 189.12,76.19 h0.76
  text "18" at 191.696,76.19 h0.76
  text "PWR" at 115.404,76.16 h0.76
  text "18" at 196.89,76.16 h0.76
  text "19" at 94.417,76.133 h0.76
  text "20" at 96.739,76.133 h0.76
  text "21" at 99.316,76.133 h0.76
  text "22" at 101.892,76.133 h0.76
  text "23" at 104.469,76.133 h0.76
  text "24" at 107.046,76.133 h0.76
  text "25" at 109.622,76.133 h0.76
  text "26" at 112.199,76.133 h0.76
  text "9" at 168.761,76.142 h0.76
  text "10" at 66.288,76.115 h0.76
  text "11" at 68.61,76.115 h0.76
  text "12" at 71.187,76.115 h0.76
  text "13" at 73.763,76.115 h0.76
  text "14" at 76.34,76.115 h0.76
  text "15" at 78.917,76.115 h0.76
  text "16" at 81.493,76.115 h0.76
  text "17" at 84.07,76.115 h0.76
  text "18" at 86.646,76.115 h0.76
  text "18" at 91.84,76.085 h0.76
  text "9" at 63.711,76.067 h0.76
  text "1" at 141.69,75.965 h0.76
  text "2" at 144.013,75.965 h0.76
  text "3" at 146.589,75.965 h0.76
  text "4" at 149.166,75.965 h0.76
  text "5" at 151.742,75.965 h0.76
  text "6" at 154.319,75.965 h0.76
  text "7" at 156.895,75.965 h0.76
  text "8" at 159.472,75.965 h0.76
  text "9" at 162.048,75.965 h0.76
  text "0" at 139.113,75.917 h0.76
  text "1" at 36.64,75.89 h0.76
  text "2" at 38.963,75.89 h0.76
  text "3" at 41.539,75.89 h0.76
  text "4" at 44.116,75.89 h0.76
  text "5" at 46.692,75.89 h0.76
  text "6" at 49.269,75.89 h0.76
  text "7" at 51.845,75.89 h0.76
  text "8" at 54.422,75.89 h0.76
  text "9" at 56.998,75.89 h0.76
  text "0" at 34.063,75.842 h0.76
  text "10" at 48.071,35.513 h0.76
  text "12" at 50.899,35.504 h0.76
  text "14" at 53.819,35.504 h0.76
  text "10" at 153.196,35.388 h0.76
  text "14" at 158.944,35.379 h0.76
  text "12" at 156.024,35.379 h0.76
  text "15" at 58.229,34.58 h0.76
  text "R2" at 55.344,34.542 h0.76
  text "9" at 46.995,34.493 h0.76
  text "8" at 45.336,34.478 h0.76
  text "11" at 49.153,34.478 h0.76
  text "13" at 52.29,34.478 h0.76
  text "15" at 163.354,34.456 h0.76
  text "R2" at 160.469,34.417 h0.76
  text "9" at 152.12,34.368 h0.76
  text "8" at 150.461,34.353 h0.76
  text "11" at 154.278,34.353 h0.76
  text "13" at 157.415,34.353 h0.76
  text "18" at 173.66,19.528 h0.76
  text "17" at 167.921,15.296 h0.76
  text ".Layer_Name" at 14.656,-21.806 h1.52
Top Paste:
  text ".Layer_Name" at 14.656,-21.806 h1.52
Bottom Paste:
  text ".Layer_Name" at 14.656,-21.806 h1.52
Top Solder:
  text ".Layer_Name" at 14.656,-21.806 h1.52
  text ".Layer_Name" at 14.656,-21.806 h1.52
Bottom Solder:
  text ".Layer_Name" at 14.656,-21.806 h1.52
Drill Guide:
  text ".Layer_Name" at 14.656,-21.806 h1.52
M1 Board Outline:
  lines w0.254: 18.1,90.187 18.1,60.125 ; 225.4,90.162 225.4,60.1 ; 18.1,60.125 19.175,60.125 19.175,91.262 18.1,91.262 18.1,60.125 ; 225.4,60.1 225.4,91.237 226.475,91.237 226.475,60.1 225.4,60.1 ; -0.125,-0.125 -0.125,94.725 243.825,94.725 243.825,-0.125 -0.125,-0.125
  text ".Layer_Name" at 14.656,-21.806 h1.52
M2 Board Dimensions:
  rectangle: 3.175,-10.16 12.7,-6.985
  rectangle: 0,-6.985 3.175,-3.81
  lines w0.178: 0,-6.985 25.4,-6.985 ; 3.175,-10.16 3.175,-3.81 ; 6.35,-10.16 6.35,-3.81 ; 12.7,-10.16 12.7,-3.81 ; 19.05,-10.16 19.05,-3.81 ; 0,-10.16 0,-3.81 25.4,-3.81 25.4,-10.16 0,-10.16
  text ".Layer_Name" at 14.656,-21.806 h1.52
M3 3D STEP Top:
  text ".Layer_Name" at 14.656,-21.806 h1.52
M4 3D STEP Bottom:
  text ".Layer_Name" at 14.656,-21.806 h1.52
M5 Assembly Top:
  lines w0.254: -7.417,-23.626 160.223,-23.626 ; -7.417,-18.462 160.274,-18.462 ; -7.417,-13.297 -7.417,-28.791 94.31,-28.791 160.274,-28.791 160.274,-13.297 -7.404,-13.297 -7.404,-28.791 32.614,-28.791 ; 55.194,-28.791 55.194,-13.297 ; 87.376,-18.462 87.376,-13.297 ; 108.712,-18.462 108.712,-13.297 ; 124.511,-28.956 124.511,-23.804
  text "COMPONENTS MARKED 'DNP' SHOULD NOT BE POPULATED." at 29.299,-8.09 h1.52
  text "ASSEMBLY VARIANT:" at 29.286,-11.024 h1.52
  text ".VariantName" at 55.601,-11.024 h1.52
  text "PCB VIEWED FROM TOP SIDE" at -5.804,-16.654 h1.52
  text "BOARD #:" at 57.099,-16.654 h1.52
  text ".PRJ_Number" at 70.955,-16.654 h1.52
  text "REV:" at 92.405,-16.654 h1.52
  text ".PCB_Rev" at 99.809,-16.654 h1.52
  text "SVN REV:" at 113.69,-16.654 h1.52
  text ".VersionControl_RevNumber" at 126.543,-16.654 h1.52
  text "PLOT NAME =" at -5.804,-27.034 h1.52
  text ".plot_File_Name" at 14.656,-27.034 h1.52
  text "GENERATED    :" at 57.15,-27.034 h1.52
  text ".Print_Date" at 79.235,-27.034 h1.52
  text ".Print_Time" at 97.752,-27.034 h1.52
  text "TEXAS INSTRUMENTS" at 129.87,-27.034 h1.52
M6 Assembly Bottom:
  lines w0.254: -7.429,-18.474 160.261,-18.474 ; -7.379,-23.639 160.261,-23.639 ; 28.334,-28.969 28.334,-23.817 ; 44.133,-18.474 44.133,-13.31 ; 65.468,-18.474 65.468,-13.31 ; 97.65,-28.804 97.65,-13.31 ; 120.231,-28.804 160.249,-28.804 160.249,-13.31 -7.429,-13.31 -7.429,-28.804 58.534,-28.804 160.261,-28.804 160.261,-13.31
  text "COMPONENTS MARKED 'DNP' SHOULD NOT BE POPULATED." at 140.12,-7.995 h1.52
  text ".VariantName" at 113.603,-10.941 h1.52
  text "ASSEMBLY VARIANT:" at 139.993,-10.941 h1.52
  text ".VersionControl_RevNumber" at 26.302,-16.667 h1.52
  text "SVN REV:" at 39.154,-16.667 h1.52
  text ".PCB_Rev" at 53.035,-16.667 h1.52
  text "REV:" at 60.439,-16.667 h1.52
  text ".PRJ_Number" at 81.89,-16.667 h1.52
  text "BOARD #:" at 95.745,-16.667 h1.52
  text "PCB VIEWED FROM BOTTOM SIDE" at 158.648,-16.667 h1.52
  text "TEXAS INSTRUMENTS" at 22.974,-27.047 h1.52
  text ".Print_Time" at 55.093,-27.047 h1.52
  text ".Print_Date" at 73.609,-27.047 h1.52
  text "GENERATED    :" at 95.694,-27.047 h1.52
  text ".plot_File_Name" at 138.189,-27.047 h1.52
  text "PLOT NAME =" at 158.648,-27.047 h1.52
